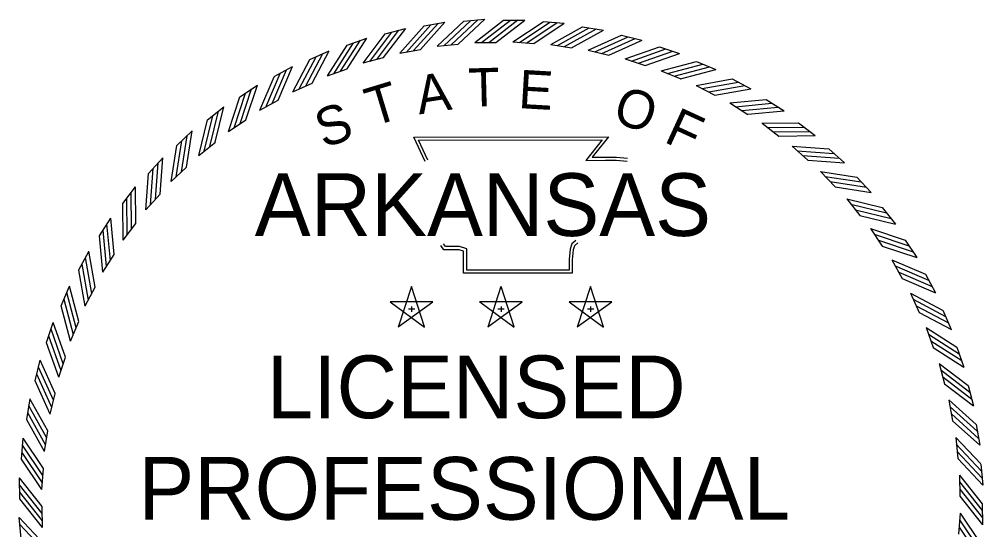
# Model space of a CAD drawing. Extents: x 18 to 14744716, y -5 to 1829144.
# Drawn here: x 42.058 to 44.124, y -3.074 to -1.98 of the extents above; entities that cross this region are included whole.
import ezdxf

# ---------------------------------------------------------------- set-up
doc = ezdxf.new("R2010")
doc.units = 0
doc.layers.add('B_StampERBB', color=7, linetype='Continuous')

msp = doc.modelspace()

# ---------------------------------------------------------------- linework, layer by layer
at = {"layer": 'B_StampERBB'}
for p, q in [((43.011, -1.9842), (43.0561, -1.98)), ((43.0967, -1.9816), (43.1419, -1.9816)), ((42.8428, -2.0113), (42.8865, -1.9998)), ((42.9263, -1.9943), (42.9709, -1.9864)), ((43.1814, -1.985), (43.2266, -1.9883)), ((43.266, -1.996), (43.3107, -2.003)), ((42.7609, -2.0353), (42.8036, -2.0202)), ((43.3494, -2.0139), (43.3933, -2.0246)), ((42.8739, -2.0524), (42.9186, -2.0445)), ((42.954, -2.0378), (42.9991, -2.0336)), ((43.035, -2.0298), (43.0803, -2.0298)), ((43.1163, -2.0285), (43.1616, -2.0318)), ((43.1975, -2.034), (43.2423, -2.041)), ((43.431, -2.0387), (43.4739, -2.053)), ((42.6813, -2.0659), (42.7226, -2.0473)), ((42.7953, -2.0736), (42.8392, -2.0621)), ((43.278, -2.0461), (43.3221, -2.0568)), ((43.3572, -2.0648), (43.4002, -2.0792)), ((42.6045, -2.1029), (42.6441, -2.081)), ((42.7188, -2.1012), (42.7615, -2.0861)), ((43.5103, -2.0701), (43.5519, -2.0879)), ((43.4346, -2.0901), (43.4763, -2.1079)), ((42.5311, -2.1462), (42.5687, -2.1211)), ((42.6448, -2.1351), (42.6861, -2.1165)), ((43.5096, -2.1216), (43.5497, -2.1428)), ((43.5867, -2.1079), (43.6267, -2.1291)), ((42.4614, -2.1954), (42.4968, -2.1673)), ((42.5738, -2.1749), (42.6135, -2.153)), ((43.5818, -2.1592), (43.62, -2.1837)), ((43.6597, -2.152), (43.6978, -2.1763)), ((42.5064, -2.2205), (42.5441, -2.1953)), ((43.6506, -2.2027), (43.6866, -2.2302)), ((43.7289, -2.2019), (43.7648, -2.2293)), ((42.396, -2.2502), (42.429, -2.2192)), ((42.443, -2.2715), (42.4785, -2.2433)), ((43.7156, -2.2516), (43.7492, -2.282)), ((43.7937, -2.2573), (43.8272, -2.2876)), ((42.3354, -2.3102), (42.3658, -2.2766)), ((42.3839, -2.3275), (42.417, -2.2965)), ((43.7763, -2.3058), (43.8073, -2.3389)), ((43.8537, -2.3179), (43.8846, -2.3509)), ((42.28, -2.375), (42.3074, -2.339)), ((42.3298, -2.3882), (42.3602, -2.3546)), ((43.8324, -2.3648), (43.8605, -2.4003)), ((43.9084, -2.3833), (43.9366, -2.4187)), ((42.2301, -2.4441), (42.2545, -2.406)), ((42.2808, -2.4532), (42.3083, -2.4172)), ((43.8833, -2.4283), (43.9085, -2.466)), ((43.9576, -2.4529), (43.9827, -2.4906)), ((42.1861, -2.5171), (42.2072, -2.4772)), ((42.2373, -2.5221), (42.2618, -2.4839)), ((43.9289, -2.4957), (43.9509, -2.5354)), ((44.0009, -2.5264), (44.0228, -2.566)), ((42.1482, -2.5936), (42.166, -2.552)), ((42.1997, -2.5942), (42.2209, -2.5542)), ((42.899, -2.5524), (42.8707, -2.6393)), ((42.9272, -2.6392), (42.8991, -2.5523)), ((43.0909, -2.5524), (43.0626, -2.6393)), ((43.1191, -2.6392), (43.091, -2.5523)), ((43.2828, -2.5524), (43.2545, -2.6393)), ((43.311, -2.6392), (43.2828, -2.5523)), ((43.9688, -2.5666), (43.9874, -2.608)), ((42.9446, -2.5856), (42.8533, -2.5855)), ((42.8534, -2.5856), (42.9272, -2.6393)), ((42.8708, -2.6392), (42.9447, -2.5856)), ((42.8925, -2.6002), (42.9061, -2.6002)), ((42.8991, -2.5953), (42.8991, -2.6067)), ((43.1365, -2.5856), (43.0452, -2.5855)), ((43.0453, -2.5856), (43.1191, -2.6393)), ((43.0627, -2.6392), (43.1366, -2.5856)), ((43.0844, -2.6002), (43.098, -2.6002)), ((43.091, -2.5953), (43.091, -2.6067)), ((43.3284, -2.5856), (43.2371, -2.5855)), ((43.2372, -2.5856), (43.311, -2.6393)), ((43.2546, -2.6392), (43.3285, -2.5856)), ((43.2763, -2.6002), (43.2899, -2.6002)), ((43.2829, -2.5953), (43.2829, -2.6067)), ((44.038, -2.6032), (44.0565, -2.6445)), ((42.1168, -2.6728), (42.1311, -2.6299)), ((42.1682, -2.6693), (42.186, -2.6276)), ((44.0026, -2.6407), (44.0177, -2.6834)), ((44.0686, -2.6828), (44.0837, -2.7255)), ((42.143, -2.7466), (42.1573, -2.7036)), ((42.0921, -2.7545), (42.1028, -2.7105)), ((44.0302, -2.7172), (44.0418, -2.7611)), ((44.0925, -2.7647), (44.104, -2.8084)), ((42.1242, -2.8258), (42.135, -2.7818)), ((42.0741, -2.8378), (42.0812, -2.7931)), ((44.0514, -2.7958), (44.0593, -2.8404)), ((44.1096, -2.8482), (44.1174, -2.8928)), ((42.1121, -2.9063), (42.1191, -2.8615)), ((42.0632, -2.9224), (42.0665, -2.8773)), ((44.0661, -2.8758), (44.0702, -2.921)), ((44.1197, -2.9329), (44.1238, -2.9779)), ((42.1066, -2.9875), (42.11, -2.9423)), ((42.0592, -3.0076), (42.0588, -2.9623)), ((44.0741, -2.9568), (44.0745, -3.0022)), ((42.1079, -3.0689), (42.1075, -3.0235)), ((44.1228, -3.0181), (44.1232, -3.0634)), ((42.0623, -3.0928), (42.0581, -3.0478)), ((44.0753, -3.0382), (44.072, -3.0834))]:
    msp.add_line(p, q, dxfattribs=at)
for points in [[(42.9684, -2.0366), (43.0255, -1.983)], [(42.984, -2.0348), (43.0411, -1.9812)], [(42.9991, -2.0336), (43.0561, -1.98)], [(43.0349, -2.0298), (43.0966, -1.9817)], [(43.0495, -2.0299), (43.1112, -1.9818)], [(43.0652, -2.0296), (43.1269, -1.9815)], [(43.0802, -2.0297), (43.142, -1.9816)], [(42.8245, -2.0658), (42.872, -2.0035)], [(42.8391, -2.0621), (42.8866, -1.9998)], [(42.8739, -2.0525), (42.9263, -1.9943)], [(42.8882, -2.0501), (42.9407, -1.9919)], [(42.9036, -2.047), (42.9561, -1.9889)], [(42.9185, -2.0445), (42.9709, -1.9864)], [(42.9539, -2.0378), (43.011, -1.9842)], [(43.1163, -2.0285), (43.1814, -1.9851)], [(43.1308, -2.0297), (43.1959, -1.9863)], [(43.1465, -2.0305), (43.2116, -1.9871)], [(43.1615, -2.0318), (43.2266, -1.9883)], [(43.1975, -2.034), (43.2659, -1.996)], [(43.2118, -2.0364), (43.2803, -1.9984)], [(43.2274, -2.0385), (43.2959, -2.0005)], [(43.2423, -2.041), (43.3107, -2.003)], [(42.7615, -2.0861), (42.8036, -2.0201)], [(42.7953, -2.0737), (42.8427, -2.0114)], [(42.8094, -2.0701), (42.8569, -2.0078)], [(43.2779, -2.0461), (43.3493, -2.014)], [(43.2921, -2.0497), (43.3634, -2.0175)], [(43.3074, -2.0531), (43.3788, -2.0209)], [(42.7188, -2.1013), (42.7609, -2.0353)], [(42.7325, -2.0966), (42.7747, -2.0306)], [(42.7472, -2.091), (42.7894, -2.025)], [(43.322, -2.0568), (43.3934, -2.0246)], [(43.3571, -2.0649), (43.4309, -2.0387)], [(43.3709, -2.0696), (43.4447, -2.0434)], [(42.6581, -2.1293), (42.6946, -2.0601)], [(42.6723, -2.1225), (42.7088, -2.0533)], [(42.6861, -2.1165), (42.7226, -2.0473)], [(43.3859, -2.0742), (43.4597, -2.0481)], [(43.4002, -2.0791), (43.474, -2.053)], [(42.6134, -2.153), (42.6441, -2.081)], [(42.6447, -2.1351), (42.6813, -2.0659)], [(43.4345, -2.0901), (43.5102, -2.0701)], [(43.4478, -2.0959), (43.5235, -2.0759)], [(43.4624, -2.1018), (43.5381, -2.0818)], [(42.5738, -2.175), (42.6045, -2.103)], [(42.5866, -2.1681), (42.6173, -2.0961)], [(42.6002, -2.1601), (42.6309, -2.0881)], [(43.4762, -2.1078), (43.5519, -2.0879)], [(42.5441, -2.1953), (42.5687, -2.1211)], [(43.5095, -2.1216), (43.5866, -2.1079)], [(43.5223, -2.1285), (43.5994, -2.1149)], [(43.5364, -2.1356), (43.6135, -2.1219)], [(42.5064, -2.2206), (42.531, -2.1463)], [(42.5186, -2.2126), (42.5432, -2.1383)], [(42.5314, -2.2036), (42.5561, -2.1293)], [(43.5496, -2.1428), (43.6267, -2.1291)], [(42.4784, -2.2433), (42.4969, -2.1672)], [(43.5817, -2.1592), (43.6596, -2.152)], [(43.5939, -2.1672), (43.6718, -2.1599)], [(43.6073, -2.1754), (43.6853, -2.1681)], [(42.4544, -2.2626), (42.4729, -2.1865)], [(42.4665, -2.2526), (42.485, -2.1765)], [(43.6199, -2.1836), (43.6979, -2.1763)], [(42.4429, -2.2715), (42.4614, -2.1955)], [(43.6505, -2.2027), (43.7288, -2.2019)], [(42.4059, -2.3067), (42.418, -2.2294)], [(42.417, -2.2965), (42.4291, -2.2192)], [(43.662, -2.2116), (43.7403, -2.2108)], [(43.6747, -2.2209), (43.753, -2.2201)], [(43.6866, -2.2301), (43.7649, -2.2293)], [(42.3839, -2.3276), (42.396, -2.2502)], [(42.3946, -2.3177), (42.4067, -2.2404)], [(42.9281, -2.2844), (42.904, -2.2322), (43.3213, -2.2319), (43.2864, -2.2757), (43.3147, -2.2754), (43.3384, -2.2751), (43.3621, -2.2776)], [(42.9341, -2.2816), (42.9144, -2.2388), (43.3076, -2.2386), (43.2726, -2.2825), (43.3148, -2.282), (43.3381, -2.2817), (43.3614, -2.2842)], [(43.7155, -2.2516), (43.7936, -2.2573)], [(43.7262, -2.2615), (43.8043, -2.2672)], [(43.7381, -2.2718), (43.8162, -2.2774)], [(42.3499, -2.3657), (42.3556, -2.2876)], [(42.3601, -2.3546), (42.3658, -2.2765)], [(43.7492, -2.282), (43.8273, -2.2876)], [(42.3298, -2.3883), (42.3354, -2.3102)], [(42.3396, -2.3776), (42.3453, -2.2995)], [(43.7762, -2.3058), (43.8536, -2.3179)], [(43.7861, -2.3165), (43.8634, -2.3286)], [(43.7971, -2.3277), (43.8744, -2.3398)], [(42.299, -2.4291), (42.2982, -2.3508)], [(42.3082, -2.4172), (42.3074, -2.339)], [(43.8073, -2.3388), (43.8847, -2.3509)], [(42.2808, -2.4533), (42.28, -2.375)], [(42.2897, -2.4418), (42.2889, -2.3635)], [(43.8323, -2.3648), (43.9084, -2.3832)], [(43.8412, -2.3763), (43.9173, -2.3947)], [(43.8513, -2.3884), (43.9273, -2.4068)], [(42.2617, -2.4839), (42.2545, -2.406)], [(43.8605, -2.4003), (43.9366, -2.4187)], [(42.2453, -2.5099), (42.2381, -2.432)], [(42.2535, -2.4965), (42.2462, -2.4186)], [(43.8833, -2.4282), (43.9576, -2.4529)], [(42.2373, -2.5221), (42.2301, -2.4442)], [(43.2513, -2.4541), (43.2426, -2.4613), (43.2395, -2.4725), (43.2371, -2.495), (43.2371, -2.5176), (43.0174, -2.5176), (43.0174, -2.4852), (43.0174, -2.4717), (43.0023, -2.4671), (42.9718, -2.4671), (42.9678, -2.4611)], [(43.8912, -2.4404), (43.9655, -2.4651)], [(43.9002, -2.4533), (43.9745, -2.478)], [(42.2209, -2.5542), (42.2072, -2.4771)], [(43.2555, -2.4593), (43.2484, -2.4651), (43.246, -2.4737), (43.2437, -2.4953), (43.2437, -2.5242), (43.0108, -2.5242), (43.0108, -2.4852), (43.0108, -2.4766), (43.0013, -2.4737), (42.9682, -2.4737), (42.9623, -2.4647)], [(43.9085, -2.4659), (43.9828, -2.4906)], [(42.2137, -2.5674), (42.2, -2.4904)], [(43.9288, -2.4957), (44.0008, -2.5264)], [(42.1997, -2.5943), (42.1861, -2.5172)], [(42.2067, -2.5815), (42.193, -2.5044)], [(43.9358, -2.5085), (44.0078, -2.5392)], [(43.9437, -2.522), (44.0157, -2.5528)], [(43.9509, -2.5353), (44.0229, -2.566)], [(42.186, -2.6276), (42.166, -2.5519)], [(42.1741, -2.656), (42.1541, -2.5803)], [(42.1799, -2.6414), (42.1599, -2.5657)], [(43.9687, -2.5666), (44.0379, -2.6032)], [(43.9745, -2.5799), (44.0438, -2.6165)], [(42.1682, -2.6693), (42.1482, -2.5936)], [(43.9813, -2.5941), (44.0505, -2.6307)], [(43.9874, -2.6079), (44.0566, -2.6445)], [(42.1524, -2.7179), (42.1262, -2.6441)], [(42.1573, -2.7037), (42.1311, -2.6299)], [(44.0025, -2.6406), (44.0685, -2.6828)], [(42.1477, -2.7329), (42.1216, -2.6592)], [(44.0073, -2.6544), (44.0732, -2.6965)], [(42.143, -2.7467), (42.1168, -2.6729)], [(44.0128, -2.6691), (44.0788, -2.7112)], [(44.0177, -2.6833), (44.0837, -2.7255)], [(42.1312, -2.7964), (42.099, -2.7251)], [(42.1349, -2.7818), (42.1027, -2.7105)], [(44.0302, -2.7172), (44.0924, -2.7646)], [(42.1278, -2.8118), (42.0957, -2.7404)], [(44.0337, -2.7313), (44.096, -2.7787)], [(44.0381, -2.7464), (44.1003, -2.7938)], [(42.1243, -2.8259), (42.0921, -2.7545)], [(44.0418, -2.761), (44.104, -2.8084)], [(42.1166, -2.8764), (42.0787, -2.808)], [(42.1191, -2.8616), (42.0811, -2.7931)], [(44.0514, -2.7957), (44.1095, -2.8482)], [(42.1145, -2.892), (42.0766, -2.8235)], [(44.0538, -2.8101), (44.1119, -2.8625)], [(44.0568, -2.8255), (44.115, -2.8779)], [(42.1121, -2.9064), (42.0742, -2.8379)], [(44.0593, -2.8404), (44.1175, -2.8928)], [(42.1099, -2.9423), (42.0664, -2.8772)], [(44.066, -2.8758), (44.1196, -2.9328)], [(44.0672, -2.8903), (44.1208, -2.9473)], [(42.1079, -2.973), (42.0644, -2.908)], [(42.1087, -2.9573), (42.0652, -2.8923)], [(44.069, -2.9059), (44.1226, -2.963)], [(42.1067, -2.9876), (42.0632, -2.9225)], [(44.0703, -2.9209), (44.1239, -2.978)], [(42.1075, -3.0236), (42.0587, -2.9623)], [(44.074, -2.9568), (44.1227, -3.018)], [(44.074, -2.9713), (44.1227, -3.0326)], [(42.1075, -3.0387), (42.0587, -2.9774)], [(42.1079, -3.0544), (42.0592, -2.9931)], [(44.0745, -2.987), (44.1232, -3.0483)], [(42.1079, -3.0689), (42.0592, -3.0076)], [(44.0745, -3.0021), (44.1232, -3.0634)], [(42.1117, -3.1048), (42.0581, -3.0477)], [(44.0741, -3.0526), (44.1176, -3.1177)], [(44.0753, -3.0381), (44.1188, -3.1032)], [(42.1129, -3.1198), (42.0593, -3.0627)], [(44.0733, -3.0683), (44.1168, -3.1334)]]:
    msp.add_lwpolyline(points, dxfattribs=at)

# ---------------------------------------------------------------- texts
for s, rotation, p in [('T', 1.4789, (43.0217, -2.1676)), ('A', 8.6788, (42.9154, -2.184)), ('E', 356.672, (43.127, -2.1701)), ('T', 16.9015, (42.8155, -2.2101)), ('O', 341.2218, (43.3269, -2.1983)), ('S', 19.7726, (42.7108, -2.257)), ('F', 335.3628, (43.4378, -2.2417))]:
    msp.add_text(s, height=0.0823, rotation=rotation, dxfattribs=at).set_placement(p)
for s, height, p in [('ARKANSAS', 0.13433, (42.563, -2.4443)), ('LICENSED', 0.13433, (42.5885, -2.8347)), ('PROFESSIONAL', 0.134326, (42.3135, -3.0522))]:
    msp.add_text(s, height=height, dxfattribs=at).set_placement(p)

doc.saveas('drawing.dxf')
